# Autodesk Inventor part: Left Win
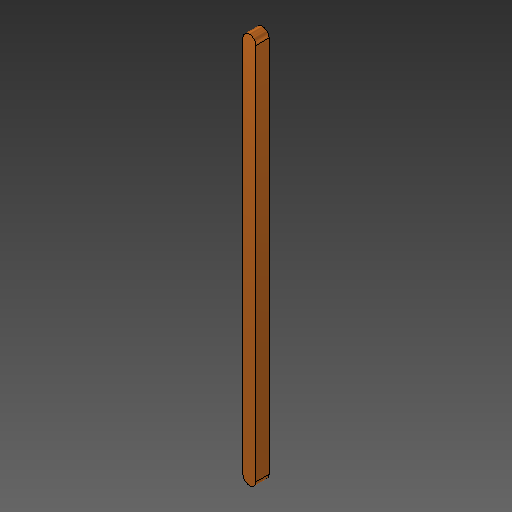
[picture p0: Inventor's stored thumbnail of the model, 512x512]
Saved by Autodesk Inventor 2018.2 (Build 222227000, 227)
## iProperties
Created: 2018-03
Part Number: Left Win
Material: Gold
Document SubType Name: Modeling
Designer: PeterMaxwell-Stewart
Mass: 70.8963 g
Surface Area: 29.7798 cm^2
Volume: 3.67338 cm^3
Density: 19.3 g/cm^3
Appearance: Metal 1600F Hot
Author: PeterMaxwell-Stewart
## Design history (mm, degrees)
derived "O's and X's.ipt"
feature "Left Win::O's and X's.ipt" dims "d0" = 10
tag "TaggingFeature1"
body "Solid1"
